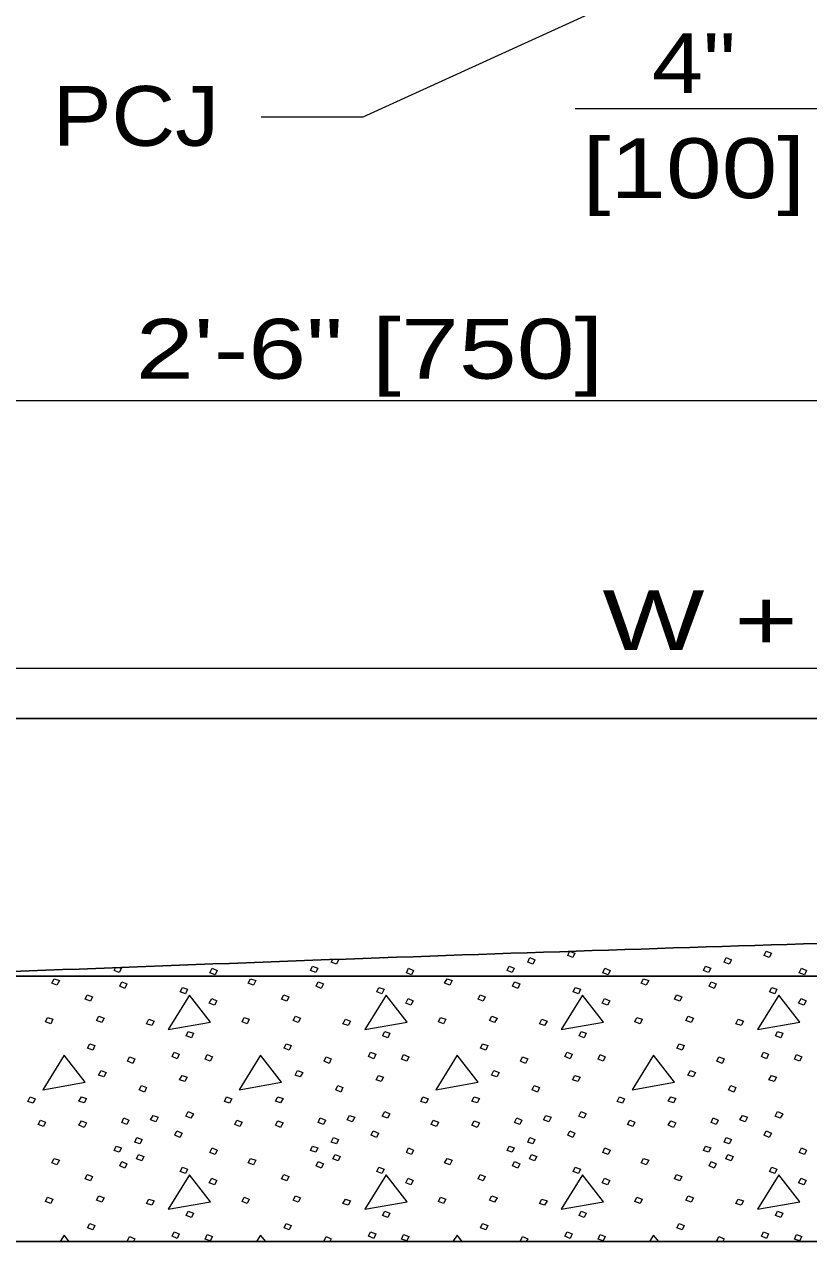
# Model space of a CAD drawing. Extents: x 1083.1 to 1123, y 697.4 to 741.4.
# Drawn here: x 1089.075 to 1091.119, y 699.494 to 702.669 of the extents above; entities that cross this region are included whole.
import ezdxf
from ezdxf.enums import TextEntityAlignment as Align

# ---------------------------------------------------------------- set-up
doc = ezdxf.new("R2010")
doc.units = 0
doc.header["$LTSCALE"] = 0.062
doc.layers.add('1', color=7, linetype='Continuous', lineweight=13)

msp = doc.modelspace()

# ---------------------------------------------------------------- linework, layer by layer
at = {"layer": '1'}
for p, q in [((1090.5105, 702.44975), (1091.42392, 702.44975)), ((1090.56375, 701.68692), (1088.74, 701.68692)), ((1091.42492, 701.68692), (1090.56375, 701.68692)), ((1094.45983, 700.98917), (1088.74, 700.98917)), ((1089.17917, 699.51175), (1089.16833, 699.49442)), ((1089.19258, 699.49442), (1089.17917, 699.51175)), ((1089.691, 699.51175), (1089.68025, 699.49442)), ((1089.7045, 699.49442), (1089.691, 699.51175)), ((1090.20283, 699.51175), (1090.19208, 699.49442)), ((1090.21633, 699.49442), (1090.20283, 699.51175)), ((1090.71475, 699.51175), (1090.70392, 699.49442)), ((1090.72817, 699.49442), (1090.71475, 699.51175))]:
    msp.add_line(p, q, dxfattribs=at)
at = {"layer": '1', "lineweight": 25}
msp.add_line((1095.16083, 700.18692), (1088.74, 700.18692), dxfattribs=at)
at = {"layer": '1'}
for points in [[(1091.42492, 703.09717), (1089.95692, 702.42633), (1089.69267, 702.42633)], [(1090.49783, 700.25142), (1090.51, 700.24633), (1090.50458, 700.235), (1090.49108, 700.24067), (1090.49625, 700.25133)], [(1089.3245, 700.20883), (1089.32817, 700.2075), (1089.32283, 700.19625), (1089.30933, 700.20108), (1089.31283, 700.20842)], [(1089.89208, 700.23017), (1089.89392, 700.22933), (1089.88858, 700.218), (1089.87508, 700.22292), (1089.87808, 700.22958)], [(1089.34892, 699.49442), (1089.34433, 699.49642), (1089.34975, 699.50767)], [(1089.34975, 699.50767), (1089.36325, 699.50208), (1089.35967, 699.49442)], [(1089.86083, 699.49442), (1089.85625, 699.49642), (1089.86158, 699.50767)], [(1089.86158, 699.50767), (1089.87508, 699.50208), (1089.8715, 699.49442)], [(1090.37267, 699.49442), (1090.36808, 699.49642), (1090.3735, 699.50767)], [(1090.3735, 699.50767), (1090.38692, 699.50208), (1090.38333, 699.49442)], [(1090.8845, 699.49442), (1090.88, 699.49642), (1090.88533, 699.50767)], [(1090.88533, 699.50767), (1090.89883, 699.50208), (1090.89525, 699.49442)]]:
    msp.add_lwpolyline(points, dxfattribs=at)
at = {"layer": '1', "lineweight": 25}
for points in [[(1094.45983, 700.85858), (1092.14192, 700.85858), (1088.75442, 700.85858)], [(1088.02083, 699.97467), (1088.02083, 699.49442), (1095.16083, 699.49442)]]:
    msp.add_lwpolyline(points, dxfattribs=at)
at = {"layer": '1'}
for points in [[(1091.00833, 700.252), (1091.02183, 700.24633), (1091.01642, 700.235), (1091.003, 700.24067)], [(1089.56442, 700.2075), (1089.57783, 700.20192), (1089.5725, 700.19058), (1089.559, 700.19542)], [(1089.82658, 700.21242), (1089.84008, 700.2075), (1089.83467, 700.19625), (1089.82125, 700.20108)], [(1090.07625, 700.2075), (1090.08975, 700.20192), (1090.08433, 700.19058), (1090.07083, 700.19542)], [(1090.33842, 700.21242), (1090.35192, 700.2075), (1090.3465, 700.19625), (1090.33308, 700.20108)], [(1090.39233, 700.235), (1090.40583, 700.22933), (1090.40042, 700.218), (1090.38692, 700.22292)], [(1090.58808, 700.2075), (1090.60158, 700.20192), (1090.59617, 700.19058), (1090.58275, 700.19542)], [(1090.85033, 700.21242), (1090.86383, 700.2075), (1090.85842, 700.19625), (1090.84492, 700.20108)], [(1090.90417, 700.235), (1090.91767, 700.22933), (1090.91225, 700.218), (1090.89883, 700.22292)], [(1091.1, 700.2075), (1091.11342, 700.20192), (1091.10808, 700.19058), (1091.09458, 700.19542)], [(1089.15308, 700.18008), (1089.16658, 700.17517), (1089.16025, 700.16308), (1089.14683, 700.16875)], [(1089.32908, 700.172), (1089.34258, 700.16633), (1089.33717, 700.155), (1089.32375, 700.16067)], [(1089.66492, 700.18008), (1089.67842, 700.17517), (1089.67217, 700.16308), (1089.65867, 700.16875)], [(1089.841, 700.172), (1089.85442, 700.16633), (1089.84908, 700.155), (1089.83558, 700.16067)], [(1090.17683, 700.18008), (1090.19025, 700.17517), (1090.184, 700.16308), (1090.1705, 700.16875)], [(1090.35283, 700.172), (1090.36633, 700.16633), (1090.36092, 700.155), (1090.34742, 700.16067)], [(1090.68867, 700.18008), (1090.70217, 700.17517), (1090.69583, 700.16308), (1090.68242, 700.16875)], [(1090.86467, 700.172), (1090.87817, 700.16633), (1090.87275, 700.155), (1090.85933, 700.16067)], [(1089.48717, 700.15742), (1089.50058, 700.15258), (1089.49525, 700.14042), (1089.48175, 700.14608)], [(1089.999, 700.15742), (1090.0125, 700.15258), (1090.00708, 700.14042), (1089.99367, 700.14608)], [(1090.51092, 700.15742), (1090.52433, 700.15258), (1090.51892, 700.14042), (1090.5055, 700.14608)], [(1091.02275, 700.15742), (1091.03617, 700.15258), (1091.03083, 700.14042), (1091.01733, 700.14608)], [(1089.23933, 700.138), (1089.25275, 700.13317), (1089.24742, 700.12183), (1089.23392, 700.12675)], [(1089.506, 700.13725), (1089.45033, 700.0475), (1089.56083, 700.06692)], [(1089.5635, 700.12833), (1089.57692, 700.12267), (1089.57067, 700.11133), (1089.55717, 700.11625)], [(1089.75117, 700.138), (1089.76467, 700.13317), (1089.75925, 700.12183), (1089.74575, 700.12675)], [(1090.01783, 700.13725), (1089.96217, 700.0475), (1090.07267, 700.06692)], [(1090.07533, 700.12833), (1090.08883, 700.12267), (1090.0825, 700.11133), (1090.06908, 700.11625)], [(1090.263, 700.138), (1090.2765, 700.13317), (1090.27108, 700.12183), (1090.25767, 700.12675)], [(1090.52975, 700.13725), (1090.47408, 700.0475), (1090.5845, 700.06692)], [(1090.58717, 700.12833), (1090.60067, 700.12267), (1090.59442, 700.11133), (1090.58092, 700.11625)], [(1090.77492, 700.138), (1090.78833, 700.13317), (1090.783, 700.12183), (1090.7695, 700.12675)], [(1091.04158, 700.13725), (1090.98592, 700.0475), (1091.09633, 700.06692)], [(1091.09908, 700.12833), (1091.1125, 700.12267), (1091.10625, 700.11133), (1091.09275, 700.11625)], [(1089.136, 700.079), (1089.1495, 700.07417), (1089.14408, 700.06283), (1089.13067, 700.06775)], [(1089.26983, 700.08225), (1089.28333, 700.07742), (1089.277, 700.06608), (1089.26358, 700.07092)], [(1089.64792, 700.079), (1089.66133, 700.07417), (1089.656, 700.06283), (1089.6425, 700.06775)], [(1089.78167, 700.08225), (1089.79517, 700.07742), (1089.78892, 700.06608), (1089.77542, 700.07092)], [(1090.15975, 700.079), (1090.17325, 700.07417), (1090.16783, 700.06283), (1090.15433, 700.06775)], [(1090.29358, 700.08225), (1090.307, 700.07742), (1090.30075, 700.06608), (1090.28725, 700.07092)], [(1090.67158, 700.079), (1090.68508, 700.07417), (1090.67967, 700.06283), (1090.66625, 700.06775)], [(1090.80542, 700.08225), (1090.81892, 700.07742), (1090.81258, 700.06608), (1090.79917, 700.07092)], [(1089.40008, 700.07417), (1089.4135, 700.06933), (1089.40725, 700.058), (1089.39375, 700.06283)], [(1089.91192, 700.07417), (1089.92542, 700.06933), (1089.91908, 700.058), (1089.90558, 700.06283)], [(1090.42375, 700.07417), (1090.43725, 700.06933), (1090.43092, 700.058), (1090.4175, 700.06283)], [(1090.93567, 700.07417), (1090.94908, 700.06933), (1090.94283, 700.058), (1090.92933, 700.06283)], [(1089.50242, 700.04267), (1089.51592, 700.03783), (1089.5105, 700.02567), (1089.497, 700.03133)], [(1090.01425, 700.04267), (1090.02775, 700.03783), (1090.02233, 700.02567), (1090.00892, 700.03133)], [(1090.52617, 700.04267), (1090.53958, 700.03783), (1090.53425, 700.02567), (1090.52075, 700.03133)], [(1091.038, 700.04267), (1091.0515, 700.03783), (1091.04608, 700.02567), (1091.03258, 700.03133)], [(1089.24558, 700.01033), (1089.25908, 700.0055), (1089.25367, 699.99417), (1089.24017, 699.999)], [(1089.46558, 699.9885), (1089.47908, 699.98367), (1089.47367, 699.97158), (1089.46025, 699.97725)], [(1089.55183, 699.98208), (1089.56525, 699.97642), (1089.55992, 699.96508), (1089.54642, 699.96992)], [(1089.75742, 700.01033), (1089.77092, 700.0055), (1089.7655, 699.99417), (1089.75208, 699.999)], [(1089.9775, 699.9885), (1089.99092, 699.98367), (1089.98558, 699.97158), (1089.97208, 699.97725)], [(1090.06367, 699.98208), (1090.07717, 699.97642), (1090.07175, 699.96508), (1090.05825, 699.96992)], [(1090.26933, 700.01033), (1090.28275, 700.0055), (1090.27742, 699.99417), (1090.26392, 699.999)], [(1090.48933, 699.9885), (1090.50283, 699.98367), (1090.49742, 699.97158), (1090.48392, 699.97725)], [(1090.5755, 699.98208), (1090.589, 699.97642), (1090.58358, 699.96508), (1090.57017, 699.96992)], [(1090.78117, 700.01033), (1090.79467, 700.0055), (1090.78925, 699.99417), (1090.77575, 699.999)], [(1091.00117, 699.9885), (1091.01467, 699.98367), (1091.00925, 699.97158), (1090.99583, 699.97725)], [(1091.08742, 699.98208), (1091.10083, 699.97642), (1091.0955, 699.96508), (1091.082, 699.96992)], [(1089.17917, 699.98042), (1089.1235, 699.89075), (1089.23392, 699.91017)], [(1089.34975, 699.97642), (1089.36325, 699.97075), (1089.35783, 699.95942), (1089.34433, 699.96508)], [(1089.691, 699.98042), (1089.63533, 699.89075), (1089.74575, 699.91017)], [(1089.86158, 699.97642), (1089.87508, 699.97075), (1089.86967, 699.95942), (1089.85625, 699.96508)], [(1090.20283, 699.98042), (1090.14717, 699.89075), (1090.25767, 699.91017)], [(1090.3735, 699.97642), (1090.38692, 699.97075), (1090.38158, 699.95942), (1090.36808, 699.96508)], [(1090.71475, 699.98042), (1090.65908, 699.89075), (1090.7695, 699.91017)], [(1090.88533, 699.97642), (1090.89883, 699.97075), (1090.89342, 699.95942), (1090.88, 699.96508)], [(1089.27525, 699.94083), (1089.28867, 699.93517), (1089.28242, 699.92383), (1089.26892, 699.92875)], [(1089.48625, 699.92792), (1089.49975, 699.92308), (1089.49342, 699.91175), (1089.48, 699.91658)], [(1089.78708, 699.94083), (1089.80058, 699.93517), (1089.79425, 699.92383), (1089.78083, 699.92875)], [(1089.99808, 699.92792), (1090.01158, 699.92308), (1090.00533, 699.91175), (1089.99183, 699.91658)], [(1090.29892, 699.94083), (1090.31242, 699.93517), (1090.30617, 699.92383), (1090.29267, 699.92875)], [(1090.51, 699.92792), (1090.52342, 699.92308), (1090.51717, 699.91175), (1090.50367, 699.91658)], [(1090.81083, 699.94083), (1090.82425, 699.93517), (1090.818, 699.92383), (1090.8045, 699.92875)], [(1091.02183, 699.92792), (1091.03533, 699.92308), (1091.029, 699.91175), (1091.01558, 699.91658)], [(1089.38025, 699.90125), (1089.39375, 699.89642), (1089.38833, 699.88425), (1089.37492, 699.88992)], [(1089.89217, 699.90125), (1089.90558, 699.89642), (1089.90025, 699.88425), (1089.88675, 699.88992)], [(1090.404, 699.90125), (1090.4175, 699.89642), (1090.41208, 699.88425), (1090.39867, 699.88992)], [(1090.91583, 699.90125), (1090.92933, 699.89642), (1090.924, 699.88425), (1090.9105, 699.88992)], [(1089.09025, 699.87217), (1089.10375, 699.8665), (1089.09833, 699.85517), (1089.08483, 699.86)], [(1089.224, 699.87217), (1089.2375, 699.86733), (1089.23125, 699.856), (1089.21775, 699.86083)], [(1089.60208, 699.87217), (1089.61558, 699.8665), (1089.61017, 699.85517), (1089.59675, 699.86)], [(1089.73592, 699.87217), (1089.74942, 699.86733), (1089.74308, 699.856), (1089.72958, 699.86083)], [(1090.114, 699.87217), (1090.12742, 699.8665), (1090.122, 699.85517), (1090.10858, 699.86)], [(1090.24775, 699.87217), (1090.26125, 699.86733), (1090.25492, 699.856), (1090.2415, 699.86083)], [(1090.62583, 699.87217), (1090.63925, 699.8665), (1090.63392, 699.85517), (1090.62042, 699.86)], [(1090.75967, 699.87217), (1090.77308, 699.86733), (1090.76683, 699.856), (1090.75333, 699.86083)], [(1089.41083, 699.82367), (1089.42433, 699.81883), (1089.418, 699.80667), (1089.4045, 699.81233)], [(1089.50242, 699.83342), (1089.51592, 699.82775), (1089.50958, 699.81642), (1089.49617, 699.82208)], [(1089.92267, 699.82367), (1089.93617, 699.81883), (1089.92983, 699.80667), (1089.91642, 699.81233)], [(1090.01425, 699.83342), (1090.02775, 699.82775), (1090.0215, 699.81642), (1090.008, 699.82208)], [(1090.4345, 699.82367), (1090.448, 699.81883), (1090.44175, 699.80667), (1090.42825, 699.81233)], [(1090.52617, 699.83342), (1090.53958, 699.82775), (1090.53333, 699.81642), (1090.51983, 699.82208)], [(1090.94642, 699.82367), (1090.95992, 699.81883), (1090.95358, 699.80667), (1090.94008, 699.81233)], [(1091.038, 699.83342), (1091.0515, 699.82775), (1091.04517, 699.81642), (1091.03175, 699.82208)], [(1089.11717, 699.81158), (1089.13067, 699.80592), (1089.12525, 699.79458), (1089.11175, 699.80025)], [(1089.224, 699.80908), (1089.2375, 699.80425), (1089.23125, 699.79217), (1089.21775, 699.79783)], [(1089.3345, 699.81725), (1089.348, 699.81158), (1089.34258, 699.80025), (1089.32908, 699.80508)], [(1089.629, 699.81158), (1089.6425, 699.80592), (1089.63708, 699.79458), (1089.62367, 699.80025)], [(1089.73592, 699.80908), (1089.74942, 699.80425), (1089.74308, 699.79217), (1089.72958, 699.79783)], [(1089.84633, 699.81725), (1089.85983, 699.81158), (1089.85442, 699.80025), (1089.841, 699.80508)], [(1090.14092, 699.81158), (1090.15433, 699.80592), (1090.149, 699.79458), (1090.1355, 699.80025)], [(1090.24775, 699.80908), (1090.26125, 699.80425), (1090.25492, 699.79217), (1090.2415, 699.79783)], [(1090.35825, 699.81725), (1090.37167, 699.81158), (1090.36633, 699.80025), (1090.35283, 699.80508)], [(1090.65275, 699.81158), (1090.66625, 699.80592), (1090.66083, 699.79458), (1090.64733, 699.80025)], [(1090.75967, 699.80908), (1090.77308, 699.80425), (1090.76683, 699.79217), (1090.75333, 699.79783)], [(1090.87008, 699.81725), (1090.88358, 699.81158), (1090.87817, 699.80025), (1090.86467, 699.80508)], [(1089.36858, 699.76625), (1089.38208, 699.76067), (1089.37667, 699.74933), (1089.36325, 699.75417)], [(1089.47275, 699.78325), (1089.48625, 699.77758), (1089.48083, 699.76625), (1089.46742, 699.77192)], [(1089.8805, 699.76625), (1089.89392, 699.76067), (1089.88858, 699.74933), (1089.87508, 699.75417)], [(1089.98467, 699.78325), (1089.99808, 699.77758), (1089.99275, 699.76625), (1089.97925, 699.77192)], [(1090.39233, 699.76625), (1090.40583, 699.76067), (1090.40042, 699.74933), (1090.38692, 699.75417)], [(1090.4965, 699.78325), (1090.51, 699.77758), (1090.50458, 699.76625), (1090.49108, 699.77192)], [(1090.90417, 699.76625), (1090.91767, 699.76067), (1090.91225, 699.74933), (1090.89883, 699.75417)], [(1091.00833, 699.78325), (1091.02183, 699.77758), (1091.01642, 699.76625), (1091.003, 699.77192)], [(1089.31475, 699.74367), (1089.32817, 699.73883), (1089.32283, 699.7275), (1089.30933, 699.73233)], [(1089.56442, 699.73883), (1089.57783, 699.73317), (1089.5725, 699.72183), (1089.559, 699.72667)], [(1089.82658, 699.74367), (1089.84008, 699.73883), (1089.83467, 699.7275), (1089.82125, 699.73233)], [(1090.07625, 699.73883), (1090.08975, 699.73317), (1090.08433, 699.72183), (1090.07083, 699.72667)], [(1090.33842, 699.74367), (1090.35192, 699.73883), (1090.3465, 699.7275), (1090.33308, 699.73233)], [(1090.58808, 699.73883), (1090.60158, 699.73317), (1090.59617, 699.72183), (1090.58275, 699.72667)], [(1090.85033, 699.74367), (1090.86383, 699.73883), (1090.85842, 699.7275), (1090.84492, 699.73233)], [(1091.1, 699.73883), (1091.11342, 699.73317), (1091.10808, 699.72183), (1091.09458, 699.72667)], [(1089.15308, 699.71133), (1089.16658, 699.7065), (1089.16025, 699.69433), (1089.14683, 699.7)], [(1089.32908, 699.70325), (1089.34258, 699.69758), (1089.33717, 699.68625), (1089.32375, 699.69192)], [(1089.37308, 699.72183), (1089.38658, 699.71617), (1089.38117, 699.70492), (1089.36775, 699.7105)], [(1089.66492, 699.71133), (1089.67842, 699.7065), (1089.67217, 699.69433), (1089.65867, 699.7)], [(1089.841, 699.70325), (1089.85442, 699.69758), (1089.84908, 699.68625), (1089.83558, 699.69192)], [(1089.885, 699.72183), (1089.89842, 699.71617), (1089.89308, 699.70492), (1089.87958, 699.7105)], [(1090.17683, 699.71133), (1090.19025, 699.7065), (1090.184, 699.69433), (1090.1705, 699.7)], [(1090.35283, 699.70325), (1090.36633, 699.69758), (1090.36092, 699.68625), (1090.34742, 699.69192)], [(1090.39683, 699.72183), (1090.41033, 699.71617), (1090.40492, 699.70492), (1090.39142, 699.7105)], [(1090.68867, 699.71133), (1090.70217, 699.7065), (1090.69583, 699.69433), (1090.68242, 699.7)], [(1090.86467, 699.70325), (1090.87817, 699.69758), (1090.87275, 699.68625), (1090.85933, 699.69192)], [(1090.90867, 699.72183), (1090.92217, 699.71617), (1090.91675, 699.70492), (1090.90333, 699.7105)], [(1089.23933, 699.66933), (1089.25275, 699.6645), (1089.24742, 699.65317), (1089.23392, 699.658)], [(1089.506, 699.6685), (1089.45033, 699.57883), (1089.56083, 699.59825)], [(1089.48717, 699.68875), (1089.50058, 699.68383), (1089.49525, 699.67175), (1089.48175, 699.67742)], [(1089.75117, 699.66933), (1089.76467, 699.6645), (1089.75925, 699.65317), (1089.74575, 699.658)], [(1090.01783, 699.6685), (1089.96217, 699.57883), (1090.07267, 699.59825)], [(1089.999, 699.68875), (1090.0125, 699.68383), (1090.00708, 699.67175), (1089.99367, 699.67742)], [(1090.263, 699.66933), (1090.2765, 699.6645), (1090.27108, 699.65317), (1090.25767, 699.658)], [(1090.52975, 699.6685), (1090.47408, 699.57883), (1090.5845, 699.59825)], [(1090.51092, 699.68875), (1090.52433, 699.68383), (1090.51892, 699.67175), (1090.5055, 699.67742)], [(1090.77492, 699.66933), (1090.78833, 699.6645), (1090.783, 699.65317), (1090.7695, 699.658)], [(1091.04158, 699.6685), (1090.98592, 699.57883), (1091.09633, 699.59825)], [(1091.02275, 699.68875), (1091.03617, 699.68383), (1091.03083, 699.67175), (1091.01733, 699.67742)], [(1089.5635, 699.65967), (1089.57692, 699.654), (1089.57067, 699.64267), (1089.55717, 699.6475)], [(1090.07533, 699.65967), (1090.08883, 699.654), (1090.0825, 699.64267), (1090.06908, 699.6475)], [(1090.58717, 699.65967), (1090.60067, 699.654), (1090.59442, 699.64267), (1090.58092, 699.6475)], [(1091.09908, 699.65967), (1091.1125, 699.654), (1091.10625, 699.64267), (1091.09275, 699.6475)], [(1089.136, 699.61033), (1089.1495, 699.6055), (1089.14408, 699.59417), (1089.13067, 699.599)], [(1089.26983, 699.61358), (1089.28333, 699.60875), (1089.277, 699.59742), (1089.26358, 699.60225)], [(1089.40008, 699.6055), (1089.4135, 699.60067), (1089.40725, 699.58933), (1089.39375, 699.59417)], [(1089.64792, 699.61033), (1089.66133, 699.6055), (1089.656, 699.59417), (1089.6425, 699.599)], [(1089.78167, 699.61358), (1089.79517, 699.60875), (1089.78892, 699.59742), (1089.77542, 699.60225)], [(1089.91192, 699.6055), (1089.92542, 699.60067), (1089.91908, 699.58933), (1089.90558, 699.59417)], [(1090.15975, 699.61033), (1090.17325, 699.6055), (1090.16783, 699.59417), (1090.15433, 699.599)], [(1090.29358, 699.61358), (1090.307, 699.60875), (1090.30075, 699.59742), (1090.28725, 699.60225)], [(1090.42375, 699.6055), (1090.43725, 699.60067), (1090.43092, 699.58933), (1090.4175, 699.59417)], [(1090.67158, 699.61033), (1090.68508, 699.6055), (1090.67967, 699.59417), (1090.66625, 699.599)], [(1090.80542, 699.61358), (1090.81892, 699.60875), (1090.81258, 699.59742), (1090.79917, 699.60225)], [(1090.93567, 699.6055), (1090.94908, 699.60067), (1090.94283, 699.58933), (1090.92933, 699.59417)], [(1089.50242, 699.574), (1089.51592, 699.56908), (1089.5105, 699.557), (1089.497, 699.56267)], [(1090.01425, 699.574), (1090.02775, 699.56908), (1090.02233, 699.557), (1090.00892, 699.56267)], [(1090.52617, 699.574), (1090.53958, 699.56908), (1090.53425, 699.557), (1090.52075, 699.56267)], [(1091.038, 699.574), (1091.0515, 699.56908), (1091.04608, 699.557), (1091.03258, 699.56267)], [(1089.24558, 699.54167), (1089.25908, 699.53675), (1089.25367, 699.5255), (1089.24017, 699.53033)], [(1089.75742, 699.54167), (1089.77092, 699.53675), (1089.7655, 699.5255), (1089.75208, 699.53033)], [(1090.26933, 699.54167), (1090.28275, 699.53675), (1090.27742, 699.5255), (1090.26392, 699.53033)], [(1090.78117, 699.54167), (1090.79467, 699.53675), (1090.78925, 699.5255), (1090.77575, 699.53033)], [(1089.46558, 699.51983), (1089.47908, 699.515), (1089.47367, 699.50283), (1089.46025, 699.5085)], [(1089.55183, 699.51333), (1089.56525, 699.50767), (1089.55992, 699.49642), (1089.54642, 699.50125)], [(1089.9775, 699.51983), (1089.99092, 699.515), (1089.98558, 699.50283), (1089.97208, 699.5085)], [(1090.06367, 699.51333), (1090.07717, 699.50767), (1090.07175, 699.49642), (1090.05825, 699.50125)], [(1090.48933, 699.51983), (1090.50283, 699.515), (1090.49742, 699.50283), (1090.48392, 699.5085)], [(1090.5755, 699.51333), (1090.589, 699.50767), (1090.58358, 699.49642), (1090.57017, 699.50125)], [(1091.00117, 699.51983), (1091.01467, 699.515), (1091.00925, 699.50283), (1090.99583, 699.5085)], [(1091.08742, 699.51333), (1091.10083, 699.50767), (1091.0955, 699.49642), (1091.082, 699.50125)]]:
    msp.add_lwpolyline(points, close=True, dxfattribs=at)
at = {"layer": '1', "lineweight": 25}
msp.add_spline([(1093.41108, 700.37683), (1093.14842, 700.34575), (1092.39425, 700.30808), (1091.48667, 700.28242), (1090.13167, 700.23908), (1088.74, 700.18692)], degree=3, dxfattribs=at)

# ---------------------------------------------------------------- texts
at = {"layer": '1'}
for s, width, p in [('4"', 1.15, (1090.81983, 702.48967)), ('[100]', 1.25, (1090.81983, 702.21567))]:
    msp.add_text(s, height=0.156, dxfattribs=dict(at, width=width)).set_placement(p, align=Align.CENTER)
for s, width, p in [('PCJ', 1.1, (1089.14942, 702.352)), ('2\'-6" [750]', 1.3, (1089.36592, 701.74475)), ('W + 4\'-4" [W+1300]', 1.35, (1090.58175, 701.03725))]:
    msp.add_text(s, height=0.156, dxfattribs=dict(at, width=width)).set_placement(p)

doc.saveas('drawing.dxf')
